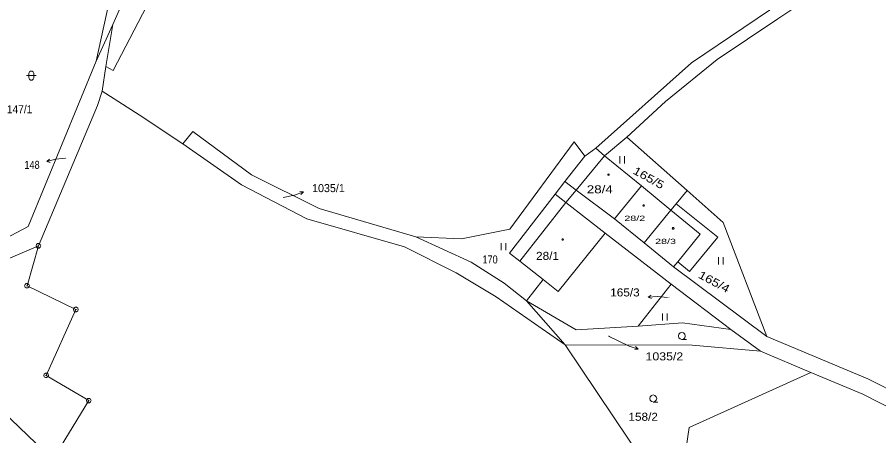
# Model space of a CAD drawing. Extents: x -687390 to -684106, y -954833 to -951648.
# Drawn here: x -686858.8 to -686675.9, y -952619.4 to -952530.5 of the extents above; entities that cross this region are included whole.
import ezdxf
from ezdxf.enums import TextEntityAlignment as Align

# ---------------------------------------------------------------- set-up
doc = ezdxf.new("R2010")
doc.units = 0
doc.header["$LTSCALE"] = 0.68
doc.header["$PDMODE"] = 32
doc.header["$PDSIZE"] = 0.34
for name, color, linetype, lineweight in [('1', 7, 'Continuous', 13), ('3', 7, 'Continuous', 13), ('4', 7, 'Continuous', 13), ('5', 7, 'Continuous', 13), ('7', 7, 'Continuous', 13), ('8', 7, 'Continuous', 13)]:
    doc.layers.add(name, color=color, linetype=linetype, lineweight=lineweight)
doc.layers.add('2', color=7, linetype='Continuous')

msp = doc.modelspace()

# ---------------------------------------------------------------- linework, layer by layer
at = {"layer": '1'}
for p, q in [((-686838.55, -952532.05), (-686827.4, -952507.1)), ((-686838.48, -952541.86), (-686830.43, -952526.36)), ((-686692.45, -952527.64), (-686697.29, -952530.86)), ((-686839.99, -952540.99), (-686838.55, -952532.05)), ((-686710.19, -952539.54), (-686697.29, -952530.86)), ((-686710.19, -952539.54), (-686721.19, -952548.46)), ((-686840.83, -952546.23), (-686839.99, -952540.99)), ((-686838.48, -952541.86), (-686839.99, -952540.99)), ((-686841.76, -952549.24), (-686840.83, -952546.23)), ((-686840.83, -952546.23), (-686832.91, -952551.26)), ((-686729.39, -952555.97), (-686721.19, -952548.46)), ((-686832.91, -952551.26), (-686823.67, -952557.38)), ((-686823.67, -952557.38), (-686821.53, -952554.81)), ((-686821.53, -952554.81), (-686809.12, -952564.02)), ((-686811.19, -952566.11), (-686823.67, -952557.38)), ((-686742.52, -952565.42), (-686738.33, -952560)), ((-686726.27, -952566.36), (-686734.09, -952559.97)), ((-686740.13, -952567.22), (-686742.52, -952565.42)), ((-686731.97, -952573.36), (-686740.13, -952567.22)), ((-686731.97, -952573.36), (-686726.27, -952566.36)), ((-686726.27, -952566.36), (-686720.01, -952571.47)), ((-686718.91, -952570.13), (-686716.58, -952567.29)), ((-686716.58, -952567.29), (-686708.9, -952574.1)), ((-686733.95, -952576.36), (-686742.34, -952569.86)), ((-686718.91, -952570.13), (-686720.01, -952571.47)), ((-686720.01, -952571.47), (-686725.71, -952578.44)), ((-686708.9, -952574.1), (-686699.62, -952598.33)), ((-686774.21, -952577.17), (-686762.41, -952582.56)), ((-686762.41, -952582.56), (-686755.43, -952586.99)), ((-686752.11, -952582.28), (-686747.16, -952586.24)), ((-686718.57, -952582.43), (-686719.47, -952583.53)), ((-686719.47, -952583.53), (-686699.62, -952598.33)), ((-686750.72, -952590.72), (-686755.43, -952586.99)), ((-686747.16, -952586.24), (-686750.72, -952590.72)), ((-686742.45, -952600.1), (-686757.12, -952589.9)), ((-686740.17, -952596.88), (-686750.72, -952590.72)), ((-686690.32, -952605.92), (-686700.99, -952601.45)), ((-686690.32, -952605.92), (-686716.16, -952617.6)), ((-686679.26, -952610.56), (-686690.32, -952605.92)), ((-686664.7, -952617.94), (-686679.26, -952610.56))]:
    msp.add_line(p, q, dxfattribs=at)
for points in [[(-686829.17, -952503.57), (-686838.84, -952524.91), (-686842.04, -952539.83), (-686838.55, -952532.05)], [(-686735.94, -952558.3), (-686715.66, -952540.23), (-686693.42, -952525.17), (-686681.74, -952519.09), (-686676.59, -952519.07)], [(-686841.76, -952549.24), (-686854.34, -952579.07), (-686866.94, -952584.44), (-686875.59, -952592.39), (-686879.48, -952588.46), (-686870, -952582.01), (-686856.5, -952574.99), (-686842.04, -952539.83)], [(-686734.09, -952559.97), (-686729.39, -952555.97), (-686716.58, -952567.29)], [(-686774.21, -952577.17), (-686764.46, -952577.58), (-686754.26, -952575.53), (-686740.58, -952556.96), (-686738.33, -952560)], [(-686734.09, -952559.97), (-686735.94, -952558.3), (-686738.33, -952560)], [(-686809.12, -952564.02), (-686794.74, -952571.12), (-686774.21, -952577.17)], [(-686742.34, -952569.86), (-686744.59, -952568.09), (-686742.52, -952565.42)], [(-686811.19, -952566.11), (-686797.33, -952573.36), (-686776.58, -952579.26), (-686765.62, -952584.79), (-686757.12, -952589.9)], [(-686752.11, -952582.28), (-686754.28, -952580.62), (-686744.59, -952568.09)], [(-686718.91, -952570.13), (-686710.04, -952577.22), (-686716.05, -952584.49), (-686718.57, -952582.43)], [(-686731.97, -952573.36), (-686725.71, -952578.44), (-686719.47, -952583.53)], [(-686740.17, -952596.88), (-686727, -952596.14), (-686720, -952587.18), (-686733.95, -952576.36)], [(-686839.31, -952639.02), (-686850.74, -952632.05), (-686855.56, -952628.43), (-686864.93, -952618.3), (-686863.78, -952612.42), (-686851.28, -952624.39), (-686843.65, -952611.91), (-686852.69, -952606.57), (-686846.38, -952592.59), (-686856.76, -952587.54), (-686854.34, -952579.07)], [(-686720, -952587.18), (-686707.29, -952596.82), (-686717.53, -952595.37), (-686727, -952596.14)], [(-686707.29, -952596.82), (-686700.99, -952601.45), (-686715.54, -952600.16), (-686742.45, -952600.1), (-686750.72, -952590.72)], [(-686699.62, -952598.33), (-686678.18, -952607.31), (-686663.65, -952614.62), (-686645, -952625.95), (-686609.97, -952643.03)], [(-686742.45, -952600.1), (-686718.74, -952635.39), (-686716.16, -952617.6)]]:
    msp.add_lwpolyline(points, dxfattribs=at)
at = {"layer": '3'}
for p, q in [((-686730.85, -952560.06), (-686730.85, -952561.56)), ((-686729.85, -952561.56), (-686729.85, -952560.06)), ((-686756.09, -952578.46), (-686756.09, -952579.96)), ((-686755.09, -952579.96), (-686755.09, -952578.46)), ((-686709.89, -952581.49), (-686709.89, -952582.99)), ((-686708.89, -952582.99), (-686708.89, -952581.49)), ((-686721.82, -952593.41), (-686721.82, -952594.91)), ((-686720.82, -952594.91), (-686720.82, -952593.41))]:
    msp.add_line(p, q, dxfattribs=at)
for points in [[(-686856.85, -952542.93), (-686855.58, -952542.93), (-686854.85, -952542.93)], [(-686717.69, -952598.93), (-686718.07, -952598.83), (-686718.34, -952598.56), (-686718.44, -952598.19), (-686718.34, -952597.82), (-686718.07, -952597.55), (-686717.7, -952597.45), (-686717.33, -952597.55), (-686717.06, -952597.82), (-686716.96, -952598.2), (-686717.06, -952598.58), (-686717.33, -952598.85), (-686717.71, -952598.95), (-686716.71, -952598.95)], [(-686723.77, -952612.19), (-686724.15, -952612.09), (-686724.42, -952611.82), (-686724.52, -952611.45), (-686724.42, -952611.08), (-686724.15, -952610.81), (-686723.78, -952610.71), (-686723.41, -952610.81), (-686723.14, -952611.08), (-686723.04, -952611.46), (-686723.14, -952611.84), (-686723.41, -952612.11), (-686723.79, -952612.21), (-686722.79, -952612.21)]]:
    msp.add_lwpolyline(points, dxfattribs=at)
msp.add_lwpolyline([(-686856.35, -952542.43), (-686856.25, -952542.14), (-686856, -952541.96), (-686855.69, -952541.96), (-686855.44, -952542.14), (-686855.34, -952542.43), (-686855.34, -952543.43), (-686855.44, -952543.72), (-686855.69, -952543.9), (-686856, -952543.9), (-686856.25, -952543.72), (-686856.35, -952543.43)], close=True, dxfattribs=at)
msp.add_point((-686733.27, -952563.94), dxfattribs=at)
at = {"layer": '4'}
for p, q in [((-686734.09, -952559.97), (-686740.13, -952567.22)), ((-686742.34, -952569.86), (-686740.13, -952567.22)), ((-686742.34, -952569.86), (-686752.11, -952582.28)), ((-686743.99, -952588.77), (-686733.95, -952576.36)), ((-686747.16, -952586.24), (-686743.99, -952588.77))]:
    msp.add_line(p, q, dxfattribs=at)
msp.add_lwpolyline([(-686720.01, -952571.47), (-686713.78, -952576.56), (-686718.57, -952582.43)], dxfattribs=at)
at = {"layer": '5'}
for points in [[(-686725.69, -952570.33), (-686725.6, -952570.48), (-686725.69, -952570.63), (-686725.87, -952570.63), (-686725.96, -952570.48), (-686725.87, -952570.33)], [(-686719.45, -952575.2), (-686719.36, -952575.35), (-686719.45, -952575.5), (-686719.63, -952575.5), (-686719.72, -952575.35), (-686719.63, -952575.2)], [(-686742.95, -952577.55), (-686742.86, -952577.7), (-686742.95, -952577.85), (-686743.13, -952577.85), (-686743.22, -952577.7), (-686743.13, -952577.55)]]:
    msp.add_lwpolyline(points, close=True, dxfattribs=at)
at = {"layer": '7'}
for p, q in [((-686852.564, -952561.189), (-686850.62, -952560.68)), ((-686848.69, -952560.46), (-686850.62, -952560.68)), ((-686802.36, -952568.8), (-686799.95, -952568.28)), ((-686798.063, -952567.588), (-686799.95, -952568.28)), ((-686724.848, -952589.923), (-686722.84, -952589.84)), ((-686720.72, -952590.05), (-686722.84, -952589.84)), ((-686733.29, -952598.25), (-686728.89, -952600.37)), ((-686726.975, -952600.98), (-686728.89, -952600.37))]:
    msp.add_line(p, q, dxfattribs=at)
for points in [[(-686851.831, -952561.344), (-686852.564, -952561.189), (-686852.001, -952560.696)], [(-686798.807, -952567.504), (-686798.063, -952567.588), (-686798.577, -952568.133)], [(-686724.165, -952590.23), (-686724.848, -952589.923), (-686724.193, -952589.56)], [(-686727.512, -952600.458), (-686726.975, -952600.98), (-686727.715, -952601.096)]]:
    msp.add_lwpolyline(points, dxfattribs=at)
at = {"layer": '8'}
for p, q in [((-686854.46, -952579.07), (-686854.22, -952579.07)), ((-686856.88, -952587.54), (-686856.64, -952587.54)), ((-686846.5, -952592.59), (-686846.26, -952592.59)), ((-686852.81, -952606.57), (-686852.57, -952606.57)), ((-686843.77, -952611.91), (-686843.53, -952611.91))]:
    msp.add_line(p, q, dxfattribs=at)
for points in [[(-686854.19, -952578.59), (-686853.94, -952578.77), (-686853.84, -952579.06), (-686853.94, -952579.35), (-686854.19, -952579.53), (-686854.5, -952579.53), (-686854.75, -952579.35), (-686854.85, -952579.06), (-686854.75, -952578.77), (-686854.5, -952578.59)], [(-686856.61, -952587.06), (-686856.36, -952587.24), (-686856.26, -952587.53), (-686856.36, -952587.82), (-686856.61, -952588), (-686856.92, -952588), (-686857.17, -952587.82), (-686857.27, -952587.53), (-686857.17, -952587.24), (-686856.92, -952587.06)], [(-686846.23, -952592.11), (-686845.98, -952592.29), (-686845.88, -952592.58), (-686845.98, -952592.87), (-686846.23, -952593.05), (-686846.54, -952593.05), (-686846.79, -952592.87), (-686846.89, -952592.58), (-686846.79, -952592.29), (-686846.54, -952592.11)], [(-686852.54, -952606.09), (-686852.29, -952606.27), (-686852.19, -952606.56), (-686852.29, -952606.85), (-686852.54, -952607.03), (-686852.85, -952607.03), (-686853.1, -952606.85), (-686853.2, -952606.56), (-686853.1, -952606.27), (-686852.85, -952606.09)], [(-686843.5, -952611.43), (-686843.25, -952611.61), (-686843.15, -952611.9), (-686843.25, -952612.19), (-686843.5, -952612.37), (-686843.81, -952612.37), (-686844.06, -952612.19), (-686844.16, -952611.9), (-686844.06, -952611.61), (-686843.81, -952611.43)]]:
    msp.add_lwpolyline(points, close=True, dxfattribs=at)

# ---------------------------------------------------------------- texts
at = {"layer": '2'}
for s, height, width, p in [('147/1', 1.7, 0.95, (-686861.035, -952550.92)), ('148', 0.1, 0.85, (-686848.644, -952560.46)), ('28/4', 1.7, 1.25, (-686737.885, -952567.91)), ('28/2', 1.1, 1.55, (-686729.913, -952573.76)), ('28/3', 1.1, 1.55, (-686723.383, -952578.66)), ('170', 1.7, 0.85, (-686760.035, -952582.8)), ('28/1', 1.7, 1.1, (-686748.655, -952582.04)), ('165/3', 0.1, 1.1, (-686720.674, -952590.05)), ('1035/2', 0.1, 1.15, (-686733.244, -952598.25)), ('158/2', 1.7, 1.1, (-686729.045, -952616.19))]:
    msp.add_text(s, height=height, dxfattribs=dict(at, width=width)).set_placement(p)
at = {"layer": '2', "width": 1.25}
for s, rotation, p in [('165/5', 330.826, (-686728.264, -952563.623)), ('165/4', 331.628, (-686714.379, -952585.743))]:
    msp.add_text(s, height=1.7, rotation=rotation, dxfattribs=at).set_placement(p)
at = {"layer": '2'}
msp.add_text('1035/1', height=0.1, dxfattribs=at).set_placement((-686802.314, -952568.8))
at = {"layer": '7'}
for s, width, p in [('148', 0.85, (-686854.076, -952562.72)), ('165/3', 1.1, (-686726.656, -952589.8))]:
    msp.add_text(s, height=1.7, dxfattribs=dict(at, width=width)).set_placement(p, align=Align.RIGHT)
msp.add_text('1035/1', height=1.7, dxfattribs=at).set_placement((-686796.225, -952567.66))
at = {"layer": '7', "width": 1.15}
msp.add_text('1035/2', height=1.7, dxfattribs=at).set_placement((-686725.405, -952603.37))

doc.saveas('drawing.dxf')
